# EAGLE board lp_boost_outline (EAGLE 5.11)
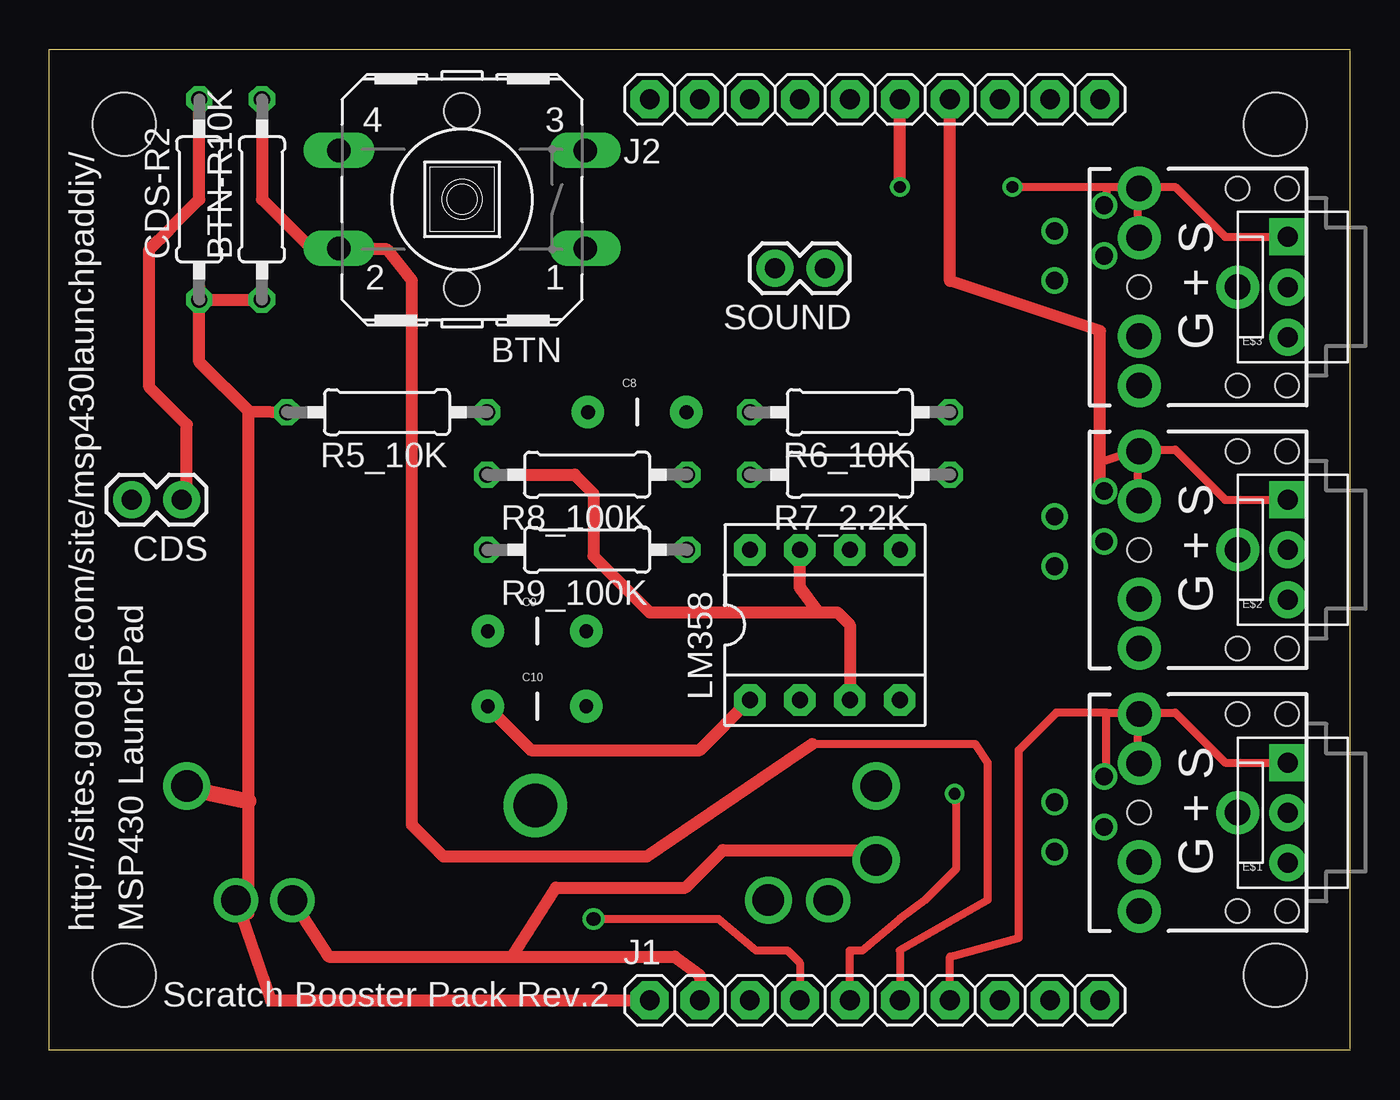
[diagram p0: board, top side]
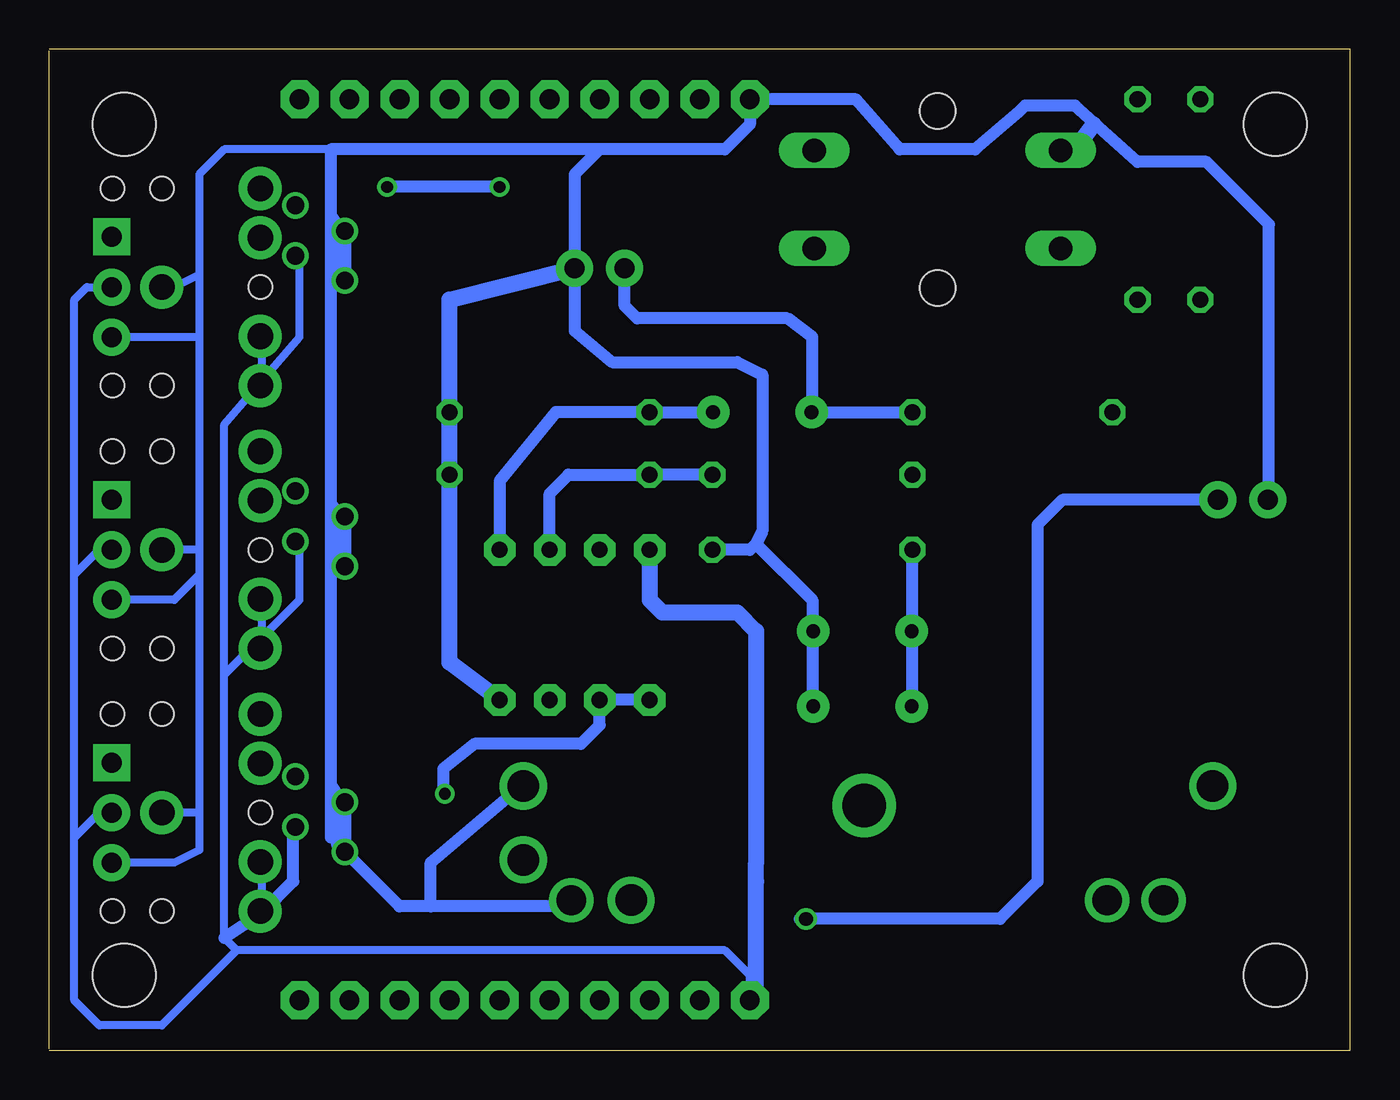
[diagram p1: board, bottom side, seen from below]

Size 66.04 x 50.8 mm. Coordinates in mm from the lower left corner, seen from the top.
Outline: 66.04,0.08 66.04,50.72
Outline: 66.04,0 0,0 0,50.8 66.04,50.8
Copper layers (1*16): Top 0.035mm / dielectric 1.5mm / Bottom 0.035mm
Design rules "default": minimum track width 10mil, minimum drill 24mil, track to track 8mil, track to pad 8mil, pad to pad 8mil, via to via 8mil, smd to smd 8mil, copper to edge 40mil, drill to drill 8mil, minimum pad ring 10mil, minimum via ring 8mil, stop-mask expansion 4mil, vias tented up to drill 0mil, thermal gap 10mil
Holes 3.2 mm at 62.23,46.99 62.23,3.81 3.81,46.99 3.81,3.81

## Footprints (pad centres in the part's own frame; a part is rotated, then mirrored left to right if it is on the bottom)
B3F-40XX = drill 1.194 long: 1 -6.248,2.489; 2 6.248,2.489; 3 -6.248,-2.489; 4 6.248,-2.489 | hole 1.803: 0,-4.496; 0,4.496
0207/10 = drill 0.813 octagon: 1 -5.08,0; 2 5.08,0
CAP-PTH-5MM = drill 0.7 pad 1.651 round: 1 -2.5,0; 2 2.5,0
1X02 = drill 1.016 pad 1.88 round: 1 0,0; 2 2.54,0
MOLEX-1X3 = drill 1.016 pad 1.88 square: 1 0,0 | drill 1.016 pad 1.88 round: 2 2.54,0; 3 5.08,0
AUDIO-JACK = drill 1.3 pad 2.184 round: RING 5,5; RSH 5,2.5; SLEEVE 0,0; TIP 5,-5; TSH 5,-2.5 | hole 1.2: 0,5; -2.5,5; -2.5,-5; 0,-5; 5,0
PH1X10OCT76 = drill 1 pad 1.93 octagon: 1 0,0; 2 2.54,0; 3 5.08,0; 4 7.62,0; 5 10.16,0; 6 12.7,0; 7 15.24,0; 8 17.78,0; 9 20.32,0; 10 22.86,0
DIL08 = drill 0.813 pad 1.6 octagon: 1 -3.81,-3.81; 2 -1.27,-3.81; 3 1.27,-3.81; 4 3.81,-3.81; 5 3.81,3.81; 6 1.27,3.81; 7 -1.27,3.81; 8 -3.81,3.81

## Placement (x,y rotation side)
BTN  [B3F-40XX]  20.95,43.18 180 top
BTN-R10K  [0207/10]  10.79,43.18 90 top
C8  0.1uF  [CAP-PTH-5MM]  29.84,32.38 0 top
C9  0.1uF  [CAP-PTH-5MM]  24.77,21.27 0 top
C10  0.1uF  [CAP-PTH-5MM]  24.77,17.46 0 top
CDS  [1X02]  6.71,27.94 180 top
CDS-R2  [0207/10]  7.62,43.18 90 top
CON-A  [MOLEX-1X3]  62.87,14.61 270 top
CON-B  [MOLEX-1X3]  62.87,27.94 270 top
CON-C  [MOLEX-1X3]  62.87,41.27 270 top
E$1  [AUDIO-JACK]  60.33,12.06 180 top
E$2  [AUDIO-JACK]  60.33,25.4 180 top
E$3  [AUDIO-JACK]  60.33,38.73 180 top
J1  [PH1X10OCT76]  30.48,2.54 0 top
J2  [PH1X10OCT76]  30.48,48.26 0 top
LM358  [DIL08]  39.37,21.59 0 top
R5_10K  [0207/10]  17.14,32.38 180 top
R6_10K  [0207/10]  40.64,32.38 180 top
R7_2.2K  [0207/10]  40.64,29.21 180 top
R8_100K  [0207/10]  27.3,29.21 180 top
R9_100K  [0207/10]  27.3,25.4 180 top
SOUND  [1X02]  39.37,39.69 180 top

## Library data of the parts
BTN = switch-omron; MF: OMRON COMPONENTS USA; MPN: B3F-4000; OC_FARNELL: 176434; OC_NEWARK: 36K3105
BTN-R10K CDS-R2 R5_10K R6_10K R7_2.2K R8_100K R9_100K = resistor
C8-C10 CDS CON-A CON-B CON-C E$1-E$3 LM358 SOUND = SparkFun
J1 J2 = MY_CONN

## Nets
!RST: J2.5
P1.0: J1.2
P1.1: J1.3
P1.4: J1.6
P1.5: CON-A.1 J1.7
P1.6: CON-B.1 J2.7
P1.7: CON-C.1 J2.6
P2.0: J1.8
P2.1: J1.9
P2.2: J1.10
P2.3: J2.10
P2.4: J2.9
P2.5: J2.8
P2.6: J2.2
P2.7: J2.3
S$10: LM358.8
S$15: R9_100K.2
S$16: J1.4
S$19: R6_10K.2
S$20: SOUND.2
S$21: BTN-R10K.1 CDS-R2.1 R5_10K.2
S$22: J1.5
S$23: LM358.4
S$24: BTN-R10K.2
S$26: LM358.6
S$27: R7_2.2K.2 R8_100K.1
S$28: LM358.3 LM358.7 R8_100K.2
S$29: LM358.1
S$31: CDS-R2.2
S$37: LM358.2
TEST: J2.4
V-: CON-A.3 CON-B.3 CON-C.3 E$1.SLEEVE E$2.SLEEVE E$3.SLEEVE J2.1 R9_100K.1 SOUND.1
VCC: CON-A.2 CON-B.2 CON-C.2 J1.1

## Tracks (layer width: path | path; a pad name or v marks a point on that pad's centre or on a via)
N$3  (via drill 2.2)
  other vias: 24.67,12.43
N$5
  Bottom 0.61: 48.26,7.3 51.44,10.48
P1.0  (via drill 1.5)
  Top 0.61: v12.34,7.62 14.19,4.76 23.5,4.76 | 23.5,4.76 31.75,4.76 33.02,3.81 J1.2 | 23.5,4.76 25.72,8.26 32.29,8.26 34.2,10.16 42.5,10.16
P1.4
  Top 0.406: 38.73,15.56 46.99,15.56 47.62,14.61 47.62,7.62 43.18,5.08 J1.6
  Top 0.61: 14.29,40.64 17.14,40.64 18.41,39.05 18.41,11.43 20,9.84 30.34,9.84 38.73,15.56
P1.5
  Top 0.406: CON-A.1 59.69,14.61 57.15,17.14 55.24,17.14 | 55.24,17.14 55.24,15.24 | 53.66,17.14 55.24,17.14 | 53.66,17.14 51.12,17.14 49.21,15.24 49.21,5.71 45.72,4.76 J1.7 | 53.66,14.29 53.66,17.14
P1.6
  Top 0.406: CON-B.1 59.69,27.94 57.15,30.48 55.24,30.48 | 55.24,30.48 55.24,28.57 | 55.24,30.48 53.34,29.84 53.34,28.57
  Top 0.61: 53.34,28.57 53.34,36.51 45.72,39.05 J2.7
P1.7  (via drill 0.6)
  Top 0.406: CON-C.1 59.69,41.27 57.15,43.81 55.24,43.81 | 55.24,43.81 55.24,41.91 | 53.66,43.81 55.24,43.81 | 53.66,43.81 53.66,42.86 | v48.9,43.81 53.66,43.81
  Top 0.61: v43.18,43.81 J2.6
  Bottom 0.61: v43.18,43.81 v48.9,43.81
S$1  (via drill 0.9)
  other vias: 51.03,27.09
S$2  (via drill 0.9)
  other vias: 51.03,24.57
S$3
  Bottom 0.813: 15.24,45.72 13.97,45.72 13.02,46.99
S$4  (via drill 0.9)
  other vias: 53.55,28.39
S$5  (via drill 0.9)
  other vias: 53.55,25.82
S$7
  Bottom 0.61: 35.88,32.38 40.32,32.38 43.18,28.89 43.18,25.4
S$8  (via drill 0.9)
  other vias: 51.03,39.06
S$9  (via drill 0.9)
  other vias: 51.03,41.58
S$10
  Bottom 0.813: LM358.8 35.56,22.86 34.92,22.23 31.11,22.23 30.16,21.27 30.16,9.53 30.16,8.57 30.16,2.54 30.48,2.22
S$11  (via drill 0.9)
  other vias: 53.55,40.32
S$12  (via drill 0.9)
  other vias: 53.55,42.88
S$13  (via drill 0.9)
  other vias: 51.03,12.6
S$14  (via drill 0.9)
  other vias: 51.03,10.07
S$15
  Bottom 0.61: 22.23,17.46 R9_100K.2
S$16  (via drill 0.7)
  Top 0.406: J1.4 38.1,4.45 37.47,5.08 35.88,5.08 33.97,6.67 v27.62,6.67
S$17  (via drill 0.9)
  other vias: 53.55,11.34
S$18  (via drill 0.9)
  other vias: 53.55,13.89
S$19
  Bottom 0.61: R6_10K.2 32.38,32.38
S$20
  Bottom 0.61: 22.23,32.38 27.3,32.38 27.3,36.2 28.57,37.15 36.2,37.15 36.83,37.78 SOUND.2
S$21
  Top 0.61: CDS-R2.1 7.62,38.73 | CDS-R2.1 7.62,34.92 10.11,32.43 | 10.11,6.94 10.11,12.65 10.11,32.43 | CDS-R2.1 BTN-R10K.1 | R5_10K.2 12.38,32.38 10.11,32.43
  Top 0.813: 6.94,13.34 10.11,12.65
S$22
  Top 0.406: J1.5 40.64,5.08 41.27,5.08 43.18,6.67 44.45,7.62 46.04,9.21 46.04,13.02
S$23
  Bottom 0.813: LM358.4 45.72,19.68 45.72,38.1 39.37,39.69
S$24
  Top 0.61: BTN-R10K.2 10.79,43.18 13.34,40.64
S$25  (via drill 1.6)
  other vias: 36.51,7.62
S$26
  Bottom 0.61: LM358.6 40.64,28.26 39.69,29.21 35.88,29.21 35.56,29.53
S$27
  Bottom 0.61: R8_100K.1 R7_2.2K.2
S$28
  Top 0.61: LM358.3 40.64,21.59 40.01,22.23 39.05,22.23 | 39.05,22.23 30.48,22.23 27.62,25.08 27.62,28.26 26.67,29.21 R8_100K.2 | LM358.7 38.1,23.5 39.05,22.23
S$29
  Top 0.61: LM358.1 33.02,15.24 24.45,15.24 22.23,17.46
S$30  (via drill 0.6)
  other vias: 45.96,13.02
S$31
  Top 0.61: 6.99,27.94 6.99,31.75 5.08,33.66 5.08,40.64 6.08,41.64 6.35,41.91 7.62,43.18 CDS-R2.2
S$32
  Bottom 0.61: 6.99,27.94 14.61,27.94 15.88,26.67 15.88,8.57 17.78,6.67 27.94,6.67
S$34  (via drill 1.5)
  other vias: 39.55,7.62
S$35
  Bottom 0.61: 42.18,13.34 46.67,9.53 46.67,7.3 | 39.64,7.3 46.67,7.3 | 46.67,7.3 48.26,7.3
S$36
  Bottom 0.61: 46.04,13.02 46.04,14.29 44.45,15.56 39.05,15.56 38.1,16.51 38.1,17.46
S$37
  Bottom 0.61: LM358.2 35.56,17.78 35.24,17.46
V-
  Bottom 0.305: 51.75,10.79 51.12,10.16 | 51.75,25.4 51.12,24.45 | 51.75,40.01 51.12,39.05
  Bottom 0.406: CON-A.3 59.69,9.53 58.42,10.16 58.42,12.06 | 58.42,12.06 E$1.SLEEVE | CON-B.3 59.69,22.86 58.42,24.13 | 58.42,24.13 58.42,12.06 | 58.42,25.4 58.42,24.13 | 58.42,25.4 E$2.SLEEVE | E$3.SLEEVE 59.69,38.73 58.42,39.37 | 58.42,36.2 58.42,25.4 | 58.42,36.2 CON-C.3 | 58.42,39.37 58.42,36.2 | 58.42,39.37 58.42,44.45 57.15,45.72 51.75,45.72 | 51.75,13.65 51.12,12.7 | 51.75,27.94 51.12,26.99 | 51.75,42.55 51.12,41.59
  Bottom 0.61: 51.75,10.79 51.75,13.65 51.75,25.4 51.75,27.94 51.75,40.01 51.75,42.55 51.75,45.72 38.1,45.72 | 38.1,45.72 31.75,45.72 30.48,46.99 J2.1 25.08,48.26 22.86,45.72 19.05,45.72 16.83,47.62 16.51,47.94 13.97,47.94 10.79,45.09 7.3,45.09 4.13,41.91 4.13,27.94 | 38.1,45.72 39.37,44.45 SOUND.1 39.37,36.51 37.47,34.92 31.11,34.92 29.84,34.29 29.84,26.35 30.16,25.72 | R9_100K.1 30.48,25.4 30.16,25.72 | 30.16,25.72 27.3,22.86 27.3,17.46
  Bottom 0.813: 51.12,26.99 51.12,24.45 | 51.12,41.59 51.12,39.05 | 51.12,12.7 51.12,10.16
VCC  (via drill 1.5, 1.6)
  Top 0.61: v9.48,7.62 11.24,2.54 J1.1
  Bottom 0.406: CON-C.2 64.14,38.73 64.77,38.1 64.77,24.13 | CON-B.2 63.5,25.4 64.77,24.13 | CON-A.2 63.5,12.06 64.77,10.79 | 53.34,40.32 53.34,36.2 55.24,33.97 | 53.66,25.72 53.34,25.4 53.34,22.86 55.24,20.95 | 55.24,33.97 55.24,35.56 | 64.77,10.79 64.77,24.13 | 64.77,10.79 64.77,2.54 63.5,1.27 60.33,1.27 56.52,5.08 | 55.24,33.97 57.15,31.75 57.15,19.05 | 55.24,20.95 55.24,22.23 | 55.24,6.99 55.24,8.89 | 57.15,19.05 55.24,20.95 | 57.15,19.05 57.15,5.71 56.52,5.08 | 56.52,5.08 31.75,5.08 30.48,3.81 J1.1
  Bottom 0.61: 53.66,11.11 53.66,8.57 55.24,6.99 57.15,5.71
  other vias: 6.98,13.42 41.98,13.42 41.98,9.67

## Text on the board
tPlace: http://sites.google.com/site/msp430launchpaddiy/ | MSP430 LaunchPad | Scratch Booster Pack Rev.2
tNames: G + S | G + S | G + S
tDocu: C | B | A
